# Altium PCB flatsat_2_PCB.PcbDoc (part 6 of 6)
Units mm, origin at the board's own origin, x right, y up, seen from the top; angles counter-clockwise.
Board outline 400 x 250 mm, 4 copper layers (Top Layer, FlatSat GND, FlatSat VCC, Bottom Layer), stack 2.102 mm thick; 196 components, 289 nets, 1724 pads, 1139 vias.
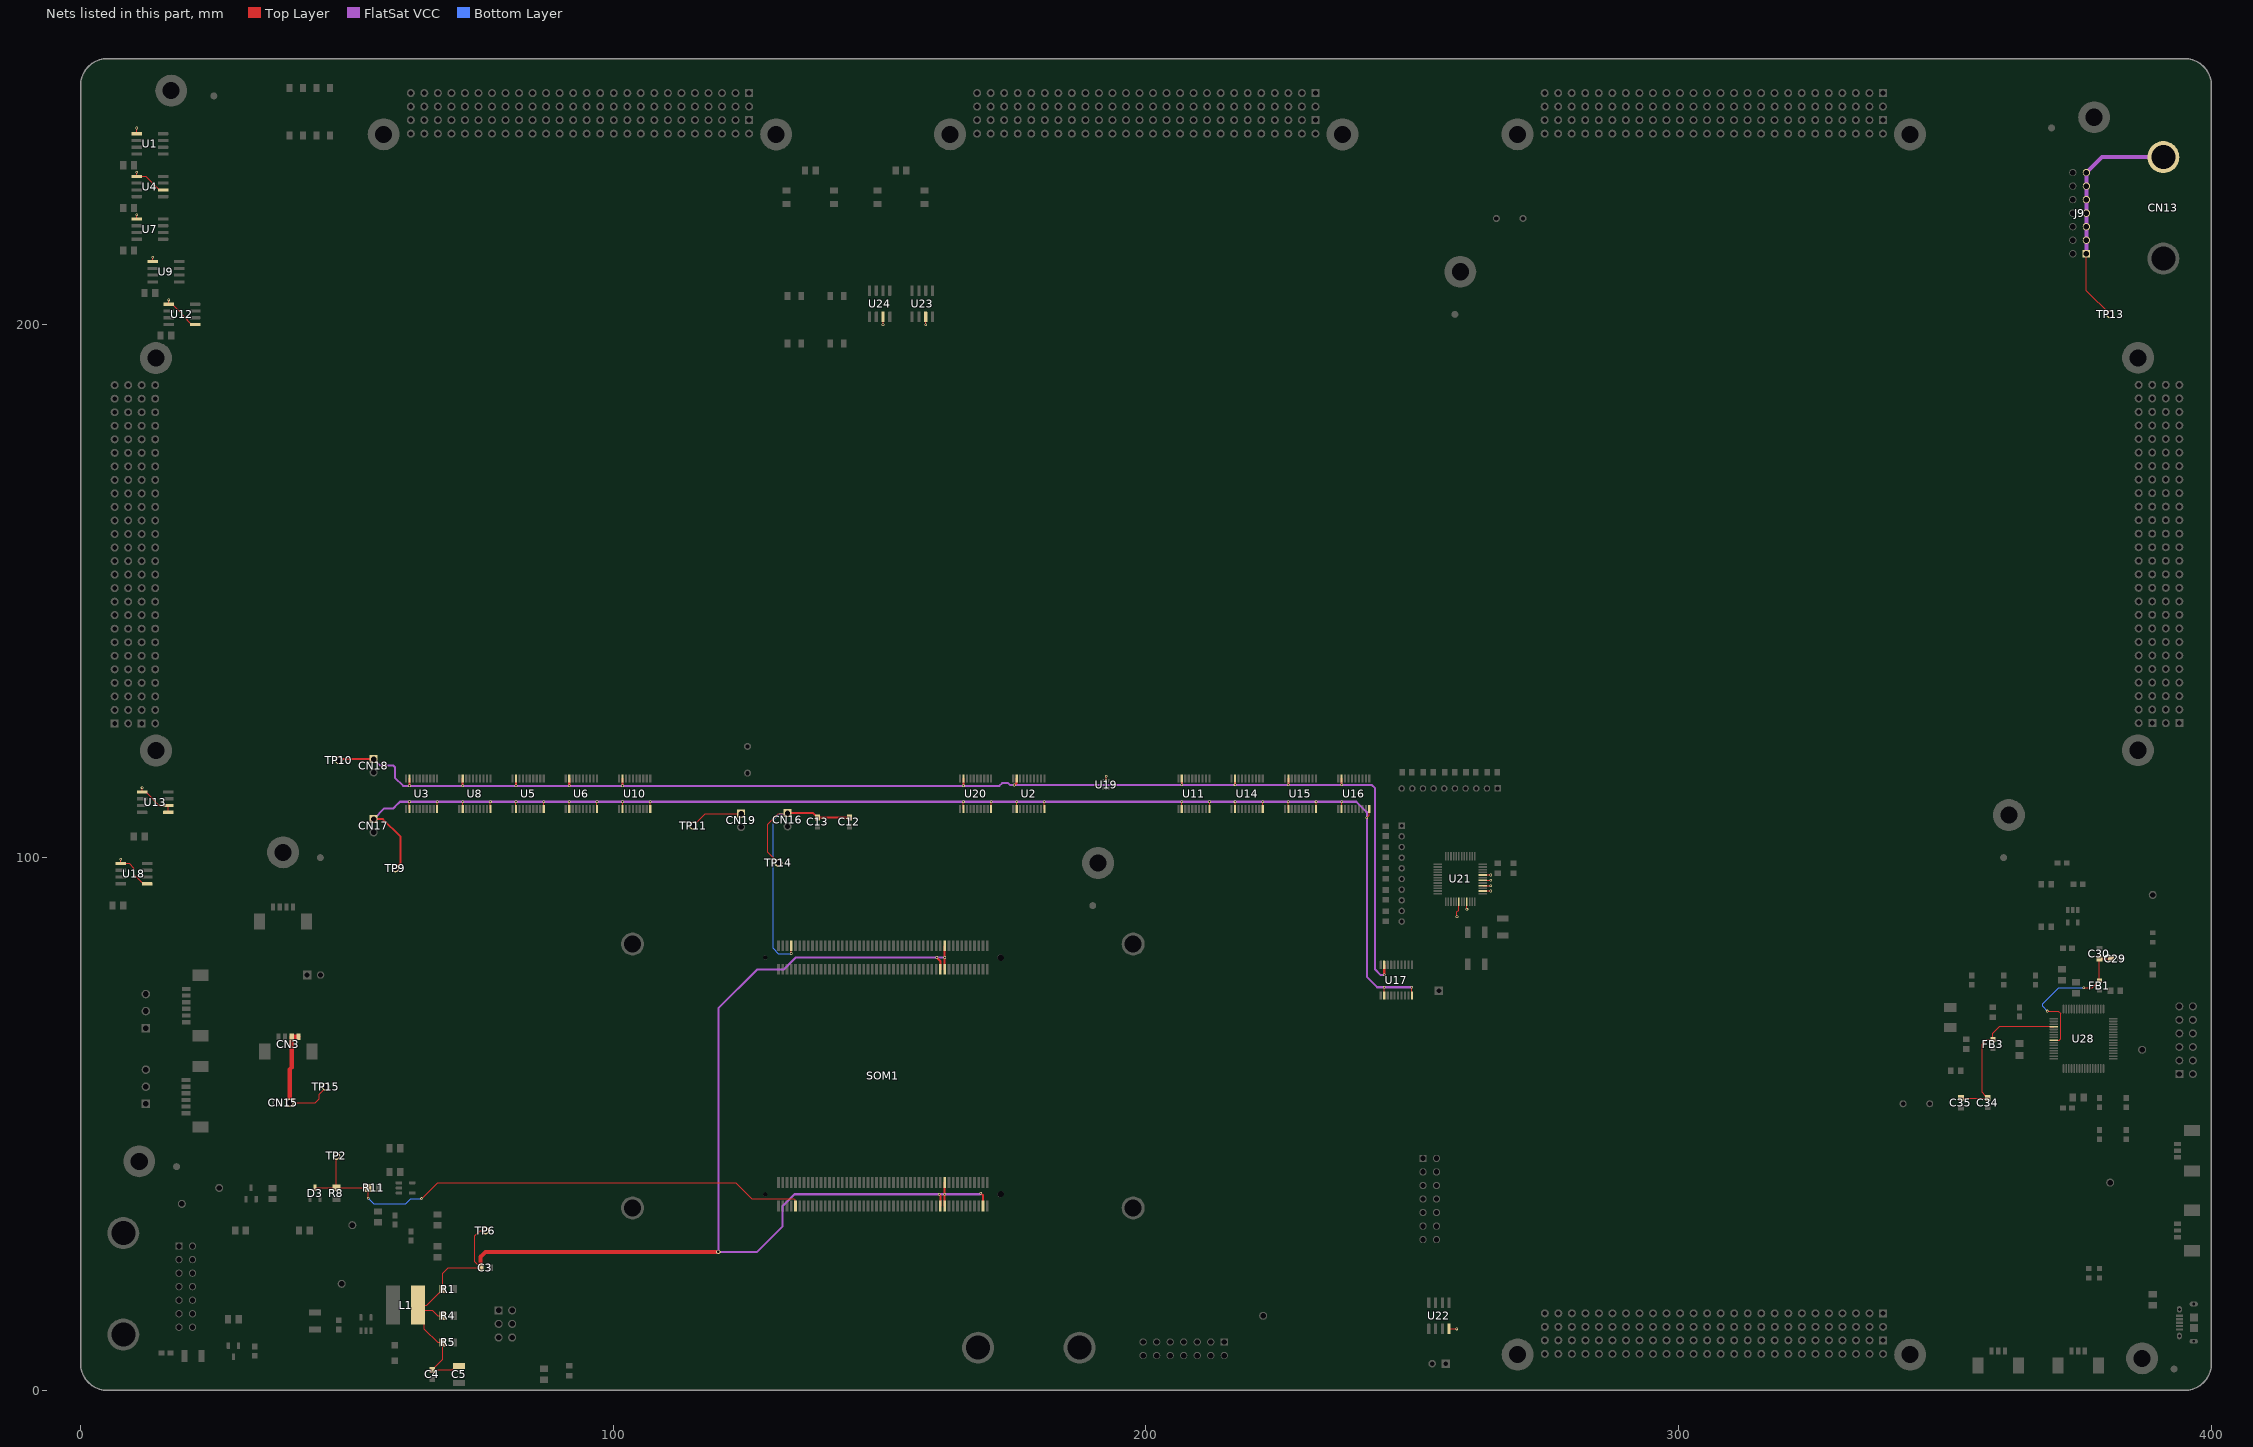
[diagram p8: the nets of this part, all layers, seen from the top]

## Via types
v1: diameter 0.508, hole 0.3, Top Layer to Bottom Layer, tented both sides, 1073 vias
v2: diameter 0.762, hole 0.45, Top Layer to Bottom Layer, tented both sides, 66 vias

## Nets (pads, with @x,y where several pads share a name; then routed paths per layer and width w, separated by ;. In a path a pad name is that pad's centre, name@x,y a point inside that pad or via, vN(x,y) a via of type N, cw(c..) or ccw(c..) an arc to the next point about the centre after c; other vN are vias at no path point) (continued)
V2_E: CN13.1 J9.1 J9.3 J9.5 J9.7 J9.9 J9.11 J9.13 TP13.1 | length 44.1
  Top Layer w0.203: J9.1@376.54,213.38 376.54,206.46 TP13.1@381,202
  FlatSat VCC w0.762: J9.1@376.54,213.38 J9.3@376.54,215.92 J9.5@376.54,218.46 J9.7@376.54,221 J9.9@376.54,223.54 J9.11@376.54,226.08 J9.13@376.54,228.62 379.445,231.525 CN13.1@391,231.525
VBAT: C12.1 C13.1 CN16.1 SOM1.JX1-7 TP14.1 | length 57.2
  Top Layer w0.203: TP14.1@131,99 129,101 129,106.285 130.985,108.27 132.616,108.27 CN16.1@132.703,108.357 ; v1(133.4,82.003) SOM1.JX1-7@133.4,83.45
  Top Layer w0.381: CN16.1@132.703,108.357 137.523,108.357 138.255,107.625 C13.1@138.33,107.625 ; C13.1@138.33,107.55 C12.1@144.33,107.55
  Bottom Layer w0.203: CN16.1@132.83,108.27 131.27,108.27 130,107 130,83 130.997,82.003 v1(133.4,82.003)
VCCA: CN17.1 TP9.1 U2.2 U2.10 U3.2 U3.10 U5.2 U5.10 U6.2 U6.10 U8.2 U8.10 U10.2 U10.10 U11.2 U11.10 U14.2 U14.10 U15.2 U15.10 U16.2 U16.10 U17.2 U17.10 U20.2 U20.10 | length 275.2
  Top Layer w0.203: U3.2@61.725,109.13 v1(61.725,110.496) ; U3.10@66.925,109.13 v1(66.925,110.496) ; U8.2@71.725,109.13 v1(71.725,110.496) ; U8.10@76.925,109.13 v1(76.925,110.496) ; U5.2@81.725,109.13 v1(81.725,110.496) ; U5.10@86.925,109.13 v1(86.925,110.496) ; U6.2@91.725,109.13 v1(91.725,110.496) ; U6.10@96.925,109.13 v1(96.925,110.496) ; U10.2@101.725,109.13 v1(101.725,110.496) ; U10.10@106.925,109.13 v1(106.925,110.496) ; U20.2@165.725,109.13 v1(165.725,110.496) ; U20.10@170.925,109.13 v1(170.925,110.496) ; U2.2@175.725,109.13 v1(175.725,110.496) ; U2.10@180.925,109.13 v1(180.925,110.496) ; U11.2@206.725,109.13 v1(206.725,110.496) ; U11.10@211.925,109.13 v1(211.925,110.496) ; U14.2@216.725,109.13 v1(216.725,110.496) ; U14.10@221.925,109.13 v1(221.925,110.496) ; U15.2@226.725,109.13 v1(226.725,110.496) ; U15.10@231.925,109.13 v1(231.925,110.496) ; U16.2@236.725,109.13 v1(236.725,110.496) ; v1(241.451,107.48) 241.925,107.953 U16.10@241.925,109.13 ; U17.2@244.725,74.13 v1(244.725,75.671) v1@244.725,75.725 ; U17.10@249.925,74.13 v1@249.925,75.725
  Top Layer w0.381: CN17.1@55,107.25 56.75,107.25 60,104 60,98.936 TP9.1@59.064,98
  FlatSat VCC w0.381: CN17.1@55,107.25 57.02,109.27 58.73,109.27 59,109.54 59.956,110.496 v1(61.725,110.496) v1(66.925,110.496) v1(71.725,110.496) v1(76.925,110.496) v1(81.725,110.496) v1(86.925,110.496) v1(91.725,110.496) v1(96.925,110.496) v1(101.725,110.496) v1(106.925,110.496) v1(165.725,110.496) v1(170.925,110.496) v1(175.725,110.496) v1(180.925,110.496) v1(206.725,110.496) v1(211.925,110.496) v1(216.725,110.496) v1(221.925,110.496) v1(226.725,110.496) v1(231.925,110.496) v1(236.725,110.496) 239.49,110.496 241.451,108.535 v1(241.451,107.48) 241.451,77.61 243.391,75.671 v1(244.725,75.671) v1(249.882,75.671)
VCCB: CN18.1 TP10.1 U2.19 U3.19 U5.19 U6.19 U8.19 U10.19 U11.19 U14.19 U15.19 U16.19 U17.19 U20.19 | length 251.2
  Top Layer w0.381: TP10.1@48.459,118.297 48.661,118.5 CN18.1@55,118.5 ; v1(61.725,113.475) U3.19@61.725,114.87 ; v1(71.725,113.475) U8.19@71.725,114.87 ; v1(81.725,113.475) U5.19@81.725,114.87 ; v1(91.725,113.475) U6.19@91.725,114.87 ; v1(101.725,113.475) U10.19@101.725,114.87 ; v1(165.725,113.475) U20.19@165.725,114.87 ; v1(175.272,113.635) 175.296,113.659 175.345,113.659 175.71,114.024 175.71,114.855 U2.19@175.725,114.87 ; v1(206.725,113.665) U11.19@206.725,114.87 ; v1(216.725,113.665) U14.19@216.725,114.87 ; v1(226.725,113.665) U15.19@226.725,114.87 ; v1(236.725,113.665) U16.19@236.725,114.87 ; v1(244.725,78) U17.19@244.725,79.87
  FlatSat VCC w0.381: CN18.1@55,118.5 56.23,117.27 58.73,117.27 59,117 59,115 60.525,113.475 v1(61.725,113.475) v1(71.725,113.475) v1(81.725,113.475) v1(91.725,113.475) v1(101.725,113.475) v1(165.725,113.475) 172.475,113.475 173,114 174.115,114 174.45,113.665 v1(206.725,113.665) v1(216.725,113.665) v1(226.725,113.665) v1(236.725,113.665) 242.335,113.665 243,113 243,79 244,78 v1(244.725,78)
VCCIO: C3.1 C4.1 C5.1 L1.2 R1.2 R4.2 R5.2 SOM1.JX1-78 SOM1.JX1-79 SOM1.JX1-80 SOM1.JX2-78 SOM1.JX2-79 SOM1.JX2-80 SOM1.JX2-98 TP6.1 | length 261.6
  Top Layer w0.203: C4.1@66,3.85 69.745,3.85 70.495,4.6 C5.1@71.045,4.6 ; C4.1@66,3.925 66.075,3.925 67.984,5.834 R5.2@67.984,9 67,9 64.543,11.457 64.543,14.806 L1.2@64.35,15 ; R4.2@67.984,14 67,14 66,15 L1.2@64.35,15 ; C3.1@75.075,23 69,23 67.984,21.984 R1.2@67.984,19 67.984,18.838 67.486,18.34 67.324,18.34 64.984,16 L1.2@63.349,16 L1.2@64.35,15 ; C3.1@75.075,23.075 74,24.15 74,29 75,30 TP6.1@76,30
  Top Layer w0.381: v1(160.737,81.263) 161.4,80.6 SOM1.JX1-78@161.4,79.05 ; v1(161.188,36.812) 161.4,36.6 SOM1.JX2-78@161.4,34.6 ; SOM1.JX2-80@162.2,34.6 v1(162.2,36.812) SOM1.JX2-79@162.2,39 ; SOM1.JX1-80@162.2,79.05 v1(162.2,81.263) SOM1.JX1-79@162.2,83.45 ; v1(169,37) 169.4,36.6 SOM1.JX2-98@169.4,34.6
  Top Layer w0.762: C3.1@75.075,23 75.075,23.075 75.075,25.075 76,26 v2(119.699,26)
  FlatSat VCC w0.381: v1(162.2,81.263) v1(160.737,81.263) 134.263,81.263 132,79 127,79 119.699,71.699 v2(119.699,26) 127,26 131.8,30.8 131.8,34.6 134.012,36.812 v1(161.188,36.812) v1(162.2,36.812) 168.812,36.812 v1(169,37)
VCCIO_EN: D3.3 R8.2 R11.2 SOM1.JX2-10 TP2.1 | length 102.7
  Top Layer w0.203: D3.3@44,38.055 R8.2@47.961,38.055 ; TP2.1@48,44 48,38.094 R8.2@47.961,38.055 ; v1(53.984,36.075) R11.2@53.984,38 53.968,38.016 R8.2@48,38.016 R8.2@47.961,38.055 ; v1(64,36) 67,39 123,39 126,36 134,36 134.119,35.881 134.119,34.681 SOM1.JX2-10@134.2,34.6
  Bottom Layer w0.203: v1(53.984,36.075) 55.059,35 61,35 62,36 v1(64,36)
VCHARG: CN3.3 CN3.4 CN15.1 TP15.1 | length 22.4
  Top Layer w0.203: CN15.1@39.25,54 44,54 44.781,54.781 44.781,55.581 TP15.1@46,56.8
  Top Layer w0.762: CN15.1@39.25,54 39.25,60.25 39.625,60.625 CN3.3@39.625,66.375 CN3.4@40.875,66.375 ; TP15.1@46,56.8 TP15.1@46,57
VPHY: C34.1 C35.1 FB3.2 U28.4 | length 31
  Top Layer w0.203: C35.1@353,54.925 353.075,54.85 C34.1@358,54.85 ; C34.1@357.925,54.925 357.502,55.348 357.502,55.423 357,55.925 357,65 357.889,65.889 FB3.2@359,65.889 359,67 360.306,68.306 369.668,68.306 369.724,68.25 U28.4@370.425,68.25
VPLL: C29.1 C30.1 FB1.2 U28.9 | length 29.4
  Top Layer w0.203: v1(369.2,71.2) 371.3,71.2 371.7,70.8 371.7,66 371.45,65.75 U28.9@370.425,65.75 ; v1(376.043,75.565) 377.626,75.565 378.95,76.889 FB1.2@379,76.889 C30.1@379,81.075 379.075,81 C29.1@381.15,81
  Bottom Layer w0.203: v1(369.2,71.2) 368.322,72.078 368.322,72.547 371.339,75.565 v1(376.043,75.565)
VS: CN19.1 TP11.1 U1.5 U4.2 U4.5 U7.5 U9.5 U12.1 U12.5 U13.1 U13.2 U13.5 U18.1 U18.5 U19.5 U21.2 U21.4 U21.6 U21.8 U21.42 U21.45 U22.8 U23.3 U24.3 | length 58.3
  Top Layer w0.203: v1(7.53,99.702) U18.5@7.53,98.905 9.095,98.905 10,98 10,96.88 11.785,95.095 U18.1@12.47,95.095 ; U7.5@10.53,219.905 v1(10.53,220.702) ; v1(10.53,228.702) U4.5@10.53,227.905 12.245,227.905 14.785,225.365 U4.2@15.47,225.365 ; U1.5@10.53,235.905 v1(10.53,236.98) ; v1(11.53,113.126) U13.5@11.53,112.328 12.215,112.328 14.755,109.788 U13.2@16.47,109.788 U13.1@16.47,108.518 ; U9.5@13.53,211.905 v1(13.53,212.702) ; v1(16.53,204.702) U12.5@16.53,203.905 17.215,203.905 19,202.12 19,202 20,201 20,200.88 20.785,200.095 U12.1@21.47,200.095 ; TP11.1@115,106 117.25,108.25 CN19.1@124,108.25 ; v1(150.635,200.07) U24.3@150.635,201.53 ; v1(158.635,200.07) U23.3@158.635,201.53 ; U19.5@192.5,114.47 192.517,114.487 192.517,115.251 v1(192.534,115.267) ; U22.8@256.905,11.525 v1(258.365,11.525) ; v1(258.379,88.935) 258.379,89.84 258.68,90.141 258.68,91.68 U21.42@258.75,91.75 ; v1(260.25,90.29) U21.45@260.25,91.75 ; U21.2@263.25,93.75 v1(264.71,93.75) ; U21.4@263.25,94.75 v1(264.71,94.75) ; U21.6@263.25,95.75 v1(264.71,95.75) ; U21.8@263.25,96.75 v1(264.71,96.75)
pads on no net: CN3.0 CN4.0 CN5.0 CN6.0 CN7.0 CN8.0 CN9.4 CN10.0 CN11.0 D2.2 D3.2 FD1.FD0 FD2.FD0 FD3.FD0 FD4.FD0 FD5.FD0 FD6.FD0 FD7.FD0 FD8.FD0 J4.14 MEC1.0 MEC2.0 MEC3.0 MEC4.0 MEC5.0 MEC6.0 MEC7.0 MEC8.0 SOM1.0 SOM1.JX1-1 SOM1.JX1-2 SOM1.JX1-3 SOM1.JX1-4 SOM1.JX1-6 SOM1.JX1-8 SOM1.JX1-9 SOM1.JX1-10 SOM1.JX1-87 SOM1.JX1-88 SOM1.JX1-89 SOM1.JX1-90 SOM1.JX1-91 SOM1.JX1-92 SOM1.JX1-93 SOM1.JX1-94 SOM1.JX2-9 SOM1.JX2-11 SOM1.JX2-13 SOM1.JX2-14 SOM1.JX2-93 SOM1.JX2-94 SOM1.JX2-95 SOM1.JX2-96 SOM1.JX2-97 SOM1.JX2-99 SOM1.JX2-100 U2.8 U2.9 U2.12 U2.13 U16.8 U16.9 U16.12 U16.13 U17.6 U17.7 U17.8 U17.9 U17.12 U17.13 U17.14 U17.15 U19.3 U20.6 U20.7 U20.8 U20.9 U20.12 U20.13 U20.14 U20.15 U21.10 U23.5 U23.8 U24.5 U24.8 U28.18 U28.19 U28.21 U28.22 U28.23 U28.24 U28.28 U28.29 U28.30 U28.32 U28.33 U28.34 U28.36 U28.40 U28.41 U28.43 U28.44 U28.45 U28.46 U28.53 U28.54 U28.55 U28.57 U28.58 U28.59 U28.60 U28.62

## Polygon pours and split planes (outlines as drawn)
VS on FlatSat VCC "VS_L03_P011" (solid, pour order 11): 0,245 cw(c5,245) 5,250 395,250 cw(c395,245) 400,245 400,5 cw(c395,5) 395,0 5,0 cw(c5,5) 0,5
USB_3.3V on FlatSat VCC "USB_3.3V_L03_P010" (solid, pour order 10): 395,0 ccw(c395,5) 400,5 400,113 341,113 341,0
5V on FlatSat VCC "5V_L03_P009" (solid, pour order 9): 5,0 cw(c5,5) 0,5 0,45 52,45 52,51 125,51 125,88 203,88 203,24 104,24 104,0
no net on FlatSat VCC "NONET_L03_P001" (solid, pour order 1): 3,159
no net on FlatSat VCC "NONET_L03_P000" (solid, pour order 0): 3,159
GND on FlatSat GND "GND_L02_P008" (solid, pour order 8): 395,0 ccw(c395,5) 400,5 400,245 ccw(c395,245) 395,250 5,250 ccw(c5,245) 0,245 0,5 ccw(c5,5) 5,0
PC104_GND on FlatSat GND "PC104_GND_L02_P007" (solid, pour order 7): 2.63,120.108 269.748,120.108 269.748,2.223 343.432,2.223 343.432,120.108 398,120.108 398,193.792 343.432,193.792 343.432,247.29 269.748,247.29 269.748,193.792 236.892,193.792 236.892,247.29 163.208,247.29 163.208,193.792 130.572,193.792 130.572,247.29 56.888,247.29 56.888,193.792 2.635,193.792 2.63,193.787
no net on FlatSat GND "NONET_L02_P005" (solid, pour order 5): 3,165
no net on FlatSat GND "NONET_L02_P004" (solid, pour order 4): 3,159
no net on FlatSat GND "NONET_L02_P003" (solid, pour order 3): 3,159
no net on FlatSat GND "NONET_L02_P002" (solid, pour order 2): 3,159
GND on Top Layer "GND_L01_P012" (solid, pour order 12): 395,250 cw(c395,245) 400,245 400,5 cw(c395,5) 395,0 5,0 cw(c5,5) 0,5 0,245 cw(c5,245) 5,250
GND on Bottom Layer "GND_L04_P013" (solid, pour order 13): 0,245 cw(c5,245) 5,250 395,250 cw(c395,245) 400,245 400,5 cw(c395,5) 395,0 5,0 cw(c5,5) 0,5

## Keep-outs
Keep-Out Layer:
  lines w0.254: 5,250 ccw(c5,245) 0,245 0,5 ccw(c5,5) 5,0 395,0 ccw(c395,5) 400,5 400,245 ccw(c395,245) 395,250 5,250 ; 5,250 5,250

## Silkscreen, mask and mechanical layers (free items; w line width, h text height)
Top Overlay:
  drawing of 1047 lines, arcs and shapes, not listed
  text "Switches for short circuit CANH and CANL with  / GND together" at 29,247 h0.5
  text "+" at 391.254,239 h1.52
  text "Switches for enable or disable terminal resistor" at 128.432,230.428 h0.5
  text "-" at 372.498,227.994 h1.52 r90
  text "+" at 379.74,227.994 h1.52 r90
  text "-" at 372.498,225.744 h1.52 r90
  text "+" at 379.74,225.744 h1.52 r90
  text "Slot 2" at 60.511,223.874 h3
  text "Slot 3" at 166.831,223.874 h3
  text "Slot 4" at 273.371,223.874 h3
  text "-" at 372.498,223.244 h1.52 r90
  text "+" at 379.74,223.244 h1.52 r90
  text "-" at 372.498,220.494 h1.52 r90
  text "+" at 379.74,220.494 h1.52 r90
  text "Switches for short circuit CANH and CANL together" at 129.1,218.267 h0.5
  text "-" at 372.498,217.994 h1.52 r90
  text "+" at 379.74,217.994 h1.52 r90
  text "-" at 372.498,215.494 h1.52 r90
  text "+" at 379.74,215.494 h1.52 r90
  text "Switches for break the CAN BUS lines" at 121.432,213.959 h0.5
  text "-" at 372.498,212.954 h1.52 r90
  text "+" at 379.74,212.954 h1.52 r90
  text "EXTERNAL  / POWER SUPPLY" at 373,211 h1.52 r270
  text "FlatSat Platform 2 / v0.1" at 289,210 h1.2
  text "SpaceLab UFSC  2021" at 287.983,207.351 h1.2
  text "-" at 391.254,204.492 h1.52
  text "Current, voltage and power sensors" at 4,201 h0.5
  text "Slot 5" at 374.319,190.224 h3 r270
  text "WARNING: Inverted PC104 pinout" at 32,127.649 h4.3 r90
  text "Slot 1" at 28.046,124.035 h3 r90
  text "Table of non-configurable PC104 pins" at 283.485,121.592 h3
  text "+" at 54.367,121.5 h1.52
  text "H" at 278.459,116.992 h2.25
  text "1" at 279.923,116.992 h2.25
  text "F" at 288.113,116.992 h2.25
  text "U" at 289.369,116.992 h2.25
  text "N" at 290.833,116.992 h2.25
  text "C" at 292.297,116.992 h2.25
  text "T" at 293.771,116.992 h2.25
  text "I" at 295.027,116.992 h2.25
  text "O" at 295.65,116.992 h2.25
  text "N" at 297.114,116.992 h2.25
  text "H" at 305.792,116.992 h2.25
  text "2" at 307.256,116.992 h2.25
  text "F" at 315.446,116.992 h2.25
  text "U" at 316.703,116.992 h2.25
  text "N" at 318.166,116.992 h2.25
  text "C" at 319.63,116.992 h2.25
  text "T" at 321.104,116.992 h2.25
  text "I" at 322.36,116.992 h2.25
  text "O" at 322.984,116.992 h2.25
  text "N" at 324.447,116.992 h2.25
  text "VCCB" at 51.746,114.254 h1.52 r90
  text "Current, voltage and power sensors" at 1.305,113.743 h0.5
  text "1" at 279.198,112.55 h2.25
  text "C" at 286.734,112.55 h2.25
  text "A" at 288.198,112.55 h2.25
  text "N" at 289.662,112.55 h2.25
  text "L" at 291.135,112.55 h2.25
  text "_" at 292.392,112.55 h2.25
  text "C" at 293.43,112.55 h2.25
  text "H" at 294.904,112.55 h2.25
  text "N" at 296.368,112.55 h2.25
  text "_" at 297.832,112.55 h2.25
  text "1" at 298.88,112.55 h2.25
  text "2" at 306.532,112.55 h2.25
  text "C" at 314.067,112.55 h2.25
  text "A" at 315.531,112.55 h2.25
  text "N" at 316.995,112.55 h2.25
  text "L" at 318.469,112.55 h2.25
  text "_" at 319.725,112.55 h2.25
  text "C" at 320.764,112.55 h2.25
  text "H" at 322.237,112.55 h2.25
  text "N" at 323.701,112.55 h2.25
  text "_" at 325.165,112.55 h2.25
  text "2" at 326.214,112.55 h2.25
  text "-" at 55.641,111.984 h1.52 r90
  text "GND" at 247.582,111.376 h0.85 r270
  text "CH9" at 249.582,111.376 h0.85 r270
  text "GND" at 251.582,111.376 h0.85 r270
  text "CH7" at 253.582,111.376 h0.85 r270
  text "GND" at 255.582,111.376 h0.85 r270
  text "CH5" at 257.582,111.376 h0.85 r270
  text "GND" at 259.582,111.376 h0.85 r270
  text "CH3" at 261.582,111.376 h0.85 r270
  text "GND" at 263.582,111.376 h0.85 r270
  text "CH1" at 265.582,111.376 h0.85 r270
  text "+" at 132.07,111.357 h1.52
  text "+" at 123.367,111.25 h1.52
  text "+" at 54.367,110.25 h1.52
  text "Ambient temperature  / sensor" at 189.378,108.47 h0.5
  text "3" at 279.198,108.109 h2.25
  text "C" at 286.624,108.109 h2.25
  text "A" at 288.088,108.109 h2.25
  text "N" at 289.552,108.109 h2.25
  text "H" at 291.025,108.109 h2.25
  text "_" at 292.489,108.109 h2.25
  text "C" at 293.538,108.109 h2.25
  text "H" at 295.002,108.109 h2.25
  text "N" at 296.466,108.109 h2.25
  text "_" at 297.93,108.109 h2.25
  text "1" at 298.978,108.109 h2.25
  text "6" at 306.532,108.109 h2.25
  text "C" at 313.957,108.109 h2.25
  text "A" at 315.421,108.109 h2.25
  text "N" at 316.885,108.109 h2.25
  text "H" at 318.359,108.109 h2.25
  text "_" at 319.823,108.109 h2.25
  text "C" at 320.871,108.109 h2.25
  text "H" at 322.335,108.109 h2.25
  text "N" at 323.799,108.109 h2.25
  text "_" at 325.263,108.109 h2.25
  text "2" at 326.312,108.109 h2.25
  text "CH11" at 249.624,105.582 h0.85
  text "3.3V" at 120.746,104.254 h1.52 r90
  text "VBAT" at 129.746,104.254 h1.52 r90
  text "2" at 278.669,103.668 h2.25
  text "9" at 279.717,103.668 h2.25
  text "G" at 291.171,103.668 h2.25
  text "N" at 292.635,103.668 h2.25
  text "D" at 294.099,103.668 h2.25
  text "2" at 306.002,103.668 h2.25
  text "5" at 307.051,103.668 h2.25
  text "P" at 312.378,103.668 h2.25
  text "A" at 313.634,103.668 h2.25
  text "Y" at 315.098,103.668 h2.25
  text "L" at 316.562,103.668 h2.25
  text "O" at 317.818,103.668 h2.25
  text "A" at 319.292,103.668 h2.25
  text "D" at 320.756,103.668 h2.25
  text "S" at 322.22,103.668 h2.25
  text "_" at 323.476,103.668 h2.25
  text "V" at 324.525,103.668 h2.25
  text "C" at 325.989,103.668 h2.25
  text "C" at 327.453,103.668 h2.25
  text "GND" at 249.624,103.582 h0.85
  text "VCCA" at 51.746,103.254 h1.52 r90
  text "-" at 133.344,101.841 h1.52 r90
  text "-" at 124.641,101.734 h1.52 r90
  text "CH13" at 249.624,101.582 h0.85
  text "-" at 55.641,100.734 h1.52 r90
  text "GND" at 249.624,99.582 h0.85
  text "3" at 278.669,99.227 h2.25
  text "0" at 279.717,99.227 h2.25
  text "G" at 291.171,99.227 h2.25
  text "N" at 292.635,99.227 h2.25
  text "D" at 294.099,99.227 h2.25
  text "2" at 306.002,99.227 h2.25
  text "6" at 307.051,99.227 h2.25
  text "P" at 312.378,99.227 h2.25
  text "A" at 313.634,99.227 h2.25
  text "Y" at 315.098,99.227 h2.25
  text "L" at 316.562,99.227 h2.25
  text "O" at 317.818,99.227 h2.25
  text "A" at 319.292,99.227 h2.25
  text "D" at 320.756,99.227 h2.25
  text "S" at 322.22,99.227 h2.25
  text "_" at 323.476,99.227 h2.25
  text "V" at 324.525,99.227 h2.25
  text "C" at 325.989,99.227 h2.25
  text "C" at 327.453,99.227 h2.25
  text "CH15" at 249.624,97.582 h0.85
  text "GND" at 249.624,95.582 h0.85
  text "3" at 278.669,94.786 h2.25
  text "1" at 279.717,94.786 h2.25
  text "G" at 291.171,94.786 h2.25
  text "N" at 292.635,94.786 h2.25
  text "D" at 294.099,94.786 h2.25
  text "2" at 306.002,94.786 h2.25
  text "7" at 307.051,94.786 h2.25
  text "E" at 313.857,94.786 h2.25
  text "P" at 315.114,94.786 h2.25
  text "S" at 316.37,94.786 h2.25
  text "_" at 317.626,94.786 h2.25
  text "B" at 318.674,94.786 h2.25
  text "E" at 320.138,94.786 h2.25
  text "_" at 321.395,94.786 h2.25
  text "V" at 322.443,94.786 h2.25
  text "C" at 323.907,94.786 h2.25
  text "C" at 325.371,94.786 h2.25
  text "CH17" at 249.624,93.582 h0.85
  text "GND" at 249.624,91.582 h0.85
  text "3" at 278.669,90.344 h2.25
  text "2" at 279.717,90.344 h2.25
  text "G" at 291.171,90.344 h2.25
  text "N" at 292.635,90.344 h2.25
  text "D" at 294.099,90.344 h2.25
  text "2" at 306.002,90.344 h2.25
  text "8" at 307.051,90.344 h2.25
  text "E" at 313.857,90.344 h2.25
  text "P" at 315.114,90.344 h2.25
  text "S" at 316.37,90.344 h2.25
  text "_" at 317.626,90.344 h2.25
  text "B" at 318.674,90.344 h2.25
  text "E" at 320.138,90.344 h2.25
  text "_" at 321.395,90.344 h2.25
  text "V" at 322.443,90.344 h2.25
  text "C" at 323.907,90.344 h2.25
  text "C" at 325.371,90.344 h2.25
  text "CH19" at 249.624,89.582 h0.85
  text "GND" at 249.624,87.582 h0.85
  text "4" at 278.669,85.903 h2.25
  text "1" at 279.717,85.903 h2.25
  text "S" at 287.473,85.903 h2.25
  text "D" at 288.73,85.903 h2.25
  text "A" at 290.193,85.903 h2.25
  text "_" at 291.657,85.903 h2.25
  text "C" at 292.706,85.903 h2.25
  text "H" at 294.17,85.903 h2.25
  text "N" at 295.644,85.903 h2.25
  text "_" at 297.107,85.903 h2.25
  text "1" at 298.156,85.903 h2.25
  text "2" at 306.002,85.903 h2.25
  text "9" at 307.051,85.903 h2.25
  text "G" at 318.505,85.903 h2.25
  text "N" at 319.968,85.903 h2.25
  text "D" at 321.432,85.903 h2.25
  text "4" at 278.669,81.462 h2.25
  text "3" at 279.717,81.462 h2.25
  text "S" at 287.583,81.462 h2.25
  text "C" at 288.839,81.462 h2.25
  text "L" at 290.303,81.462 h2.25
  text "_" at 291.56,81.462 h2.25
  text "C" at 292.608,81.462 h2.25
  text "H" at 294.072,81.462 h2.25
  text "N" at 295.536,81.462 h2.25
  text "_" at 297.01,81.462 h2.25
  text "1" at 298.048,81.462 h2.25
  text "3" at 306.002,81.462 h2.25
  text "0" at 307.051,81.462 h2.25
  text "G" at 318.505,81.462 h2.25
  text "N" at 319.968,81.462 h2.25
  text "D" at 321.432,81.462 h2.25
  text "4" at 278.669,77.021 h2.25
  text "5" at 279.717,77.021 h2.25
  text "O" at 287.683,77.021 h2.25
  text "B" at 289.147,77.021 h2.25
  text "D" at 290.611,77.021 h2.25
  text "H" at 292.085,77.021 h2.25
  text "_" at 293.549,77.021 h2.25
  text "V" at 294.597,77.021 h2.25
  text "C" at 296.061,77.021 h2.25
  text "C" at 297.525,77.021 h2.25
  text "3" at 306.002,77.021 h2.25
  text "1" at 307.051,77.021 h2.25
  text "G" at 318.505,77.021 h2.25
  text "N" at 319.968,77.021 h2.25
  text "D" at 321.432,77.021 h2.25
  text "INTERRUPT" at 256.756,75.104 h0.85
  text "RBF" at 41.728,74.545 h1.52
  text "NO" at 14.254,73.254 h1.52
  text "4" at 278.669,72.58 h2.25
  text "6" at 279.717,72.58 h2.25
  text "O" at 287.683,72.58 h2.25
  text "B" at 289.147,72.58 h2.25
  text "D" at 290.611,72.58 h2.25
  text "H" at 292.085,72.58 h2.25
  text "_" at 293.549,72.58 h2.25
  text "V" at 294.597,72.58 h2.25
  text "C" at 296.061,72.58 h2.25
  text "C" at 297.525,72.58 h2.25
  text "3" at 306.002,72.58 h2.25
  text "2" at 307.051,72.58 h2.25
  text "G" at 318.505,72.58 h2.25
  text "N" at 319.968,72.58 h2.25
  text "D" at 321.432,72.58 h2.25
  text "RX3" at 390.847,71.862 h0.5
  text "TX4" at 398.219,71.729 h0.5
  text "CM" at 14.254,70.254 h1.52
  text "TX3" at 390.847,69.322 h0.5
  text "RX4" at 398.219,69.189 h0.5
  text "4" at 278.669,68.138 h2.25
  text "7" at 279.717,68.138 h2.25
  text "E" at 288.533,68.138 h2.25
  text "D" at 289.789,68.138 h2.25
  text "C" at 291.253,68.138 h2.25
  text "_" at 292.717,68.138 h2.25
  text "V" at 293.765,68.138 h2.25
  text "C" at 295.229,68.138 h2.25
  text "C" at 296.703,68.138 h2.25
  text "3" at 306.002,68.138 h2.25
  text "5" at 307.051,68.138 h2.25
  text "A" at 315.866,68.138 h2.25
  text "N" at 317.33,68.138 h2.25
  text "T" at 318.794,68.138 h2.25
  text "_" at 320.05,68.138 h2.25
  text "V" at 321.099,68.138 h2.25
  text "C" at 322.563,68.138 h2.25
  text "C" at 324.036,68.138 h2.25
  text "NC" at 14.254,67.254 h1.52
  text "Thermocouples" at 262.99,67.229 h0.5
  text "RX2" at 390.847,66.782 h0.5
  text "GND" at 398.219,66.649 h0.5
  text "TX2" at 390.847,64.242 h0.5
  text "GND" at 398.219,64.109 h0.5
  text "4" at 278.669,63.697 h2.25
  text "8" at 279.717,63.697 h2.25
  text "E" at 288.533,63.697 h2.25
  text "D" at 289.789,63.697 h2.25
  text "C" at 291.253,63.697 h2.25
  text "_" at 292.717,63.697 h2.25
  text "V" at 293.765,63.697 h2.25
  text "C" at 295.229,63.697 h2.25
  text "C" at 296.703,63.697 h2.25
  text "3" at 306.002,63.697 h2.25
  text "6" at 307.051,63.697 h2.25
  text "A" at 315.866,63.697 h2.25
  text "N" at 317.33,63.697 h2.25
  text "T" at 318.794,63.697 h2.25
  text "_" at 320.05,63.697 h2.25
  text "V" at 321.099,63.697 h2.25
  text "C" at 322.563,63.697 h2.25
  text "C" at 324.036,63.697 h2.25
  text "RX1" at 390.847,61.702 h0.5
  text "GND" at 398.219,61.569 h0.5
  text "4" at 278.669,59.256 h2.25
  text "9" at 279.717,59.256 h2.25
  text "R" at 289.162,59.256 h2.25
  text "D" at 290.626,59.256 h2.25
  text "_" at 292.09,59.256 h2.25
  text "V" at 293.139,59.256 h2.25
  text "C" at 294.603,59.256 h2.25
  text "C" at 296.076,59.256 h2.25
  text "4" at 306.002,59.256 h2.25
  text "5" at 307.051,59.256 h2.25
  text "B" at 315.866,59.256 h2.25
  text "A" at 317.33,59.256 h2.25
  text "T" at 318.794,59.256 h2.25
  text "_" at 320.05,59.256 h2.25
  text "V" at 321.099,59.256 h2.25
  text "C" at 322.563,59.256 h2.25
  text "C" at 324.036,59.256 h2.25
  text "TX1" at 390.847,59.162 h0.5
  text "NO" at 14.26,59.054 h1.52
  text "GND" at 398.219,59.029 h0.5
  text "CM" at 14.26,56.054 h1.52
  text "5" at 278.669,54.815 h2.25
  text "0" at 279.717,54.815 h2.25
  text "R" at 289.162,54.815 h2.25
  text "D" at 290.626,54.815 h2.25
  text "_" at 292.09,54.815 h2.25
  text "V" at 293.139,54.815 h2.25
  text "C" at 294.603,54.815 h2.25
  text "C" at 296.076,54.815 h2.25
  text "4" at 306.002,54.815 h2.25
  text "6" at 307.051,54.815 h2.25
  text "B" at 315.866,54.815 h2.25
  text "A" at 317.33,54.815 h2.25
  text "T" at 318.794,54.815 h2.25
  text "_" at 320.05,54.815 h2.25
  text "V" at 321.099,54.815 h2.25
  text "C" at 322.563,54.815 h2.25
  text "C" at 324.036,54.815 h2.25
  text "+" at 42.25,54.633 h1.52 r270
  text "-" at 32.734,53.359 h1.52
  text "NC" at 14.26,53.054 h1.52
  text "5" at 278.669,50.374 h2.25
  text "1" at 279.717,50.374 h2.25
  text "B" at 287.054,50.374 h2.25
  text "E" at 288.517,50.374 h2.25
  text "_" at 289.774,50.374 h2.25
  text "R" at 290.822,50.374 h2.25
  text "F" at 292.286,50.374 h2.25
  text "_" at 293.542,50.374 h2.25
  text "V" at 294.591,50.374 h2.25
  text "C" at 296.055,50.374 h2.25
  text "C" at 297.519,50.374 h2.25
  text "4" at 306.002,50.374 h2.25
  text "9" at 307.051,50.374 h2.25
  text "S" at 314.807,50.374 h2.25
  text "D" at 316.063,50.374 h2.25
  text "A" at 317.527,50.374 h2.25
  text "_" at 318.991,50.374 h2.25
  text "C" at 320.039,50.374 h2.25
  text "H" at 321.503,50.374 h2.25
  text "N" at 322.977,50.374 h2.25
  text "_" at 324.441,50.374 h2.25
  text "2" at 325.489,50.374 h2.25
  text "CHARGE" at 34.254,48.254 h1.52
  text "5" at 278.669,45.932 h2.25
  text "2" at 279.717,45.932 h2.25
  text "B" at 287.054,45.932 h2.25
  text "E" at 288.517,45.932 h2.25
  text "_" at 289.774,45.932 h2.25
  text "R" at 290.822,45.932 h2.25
  text "F" at 292.286,45.932 h2.25
  text "_" at 293.542,45.932 h2.25
  text "V" at 294.591,45.932 h2.25
  text "C" at 296.055,45.932 h2.25
  text "C" at 297.519,45.932 h2.25
  text "5" at 306.002,45.932 h2.25
  text "1" at 307.051,45.932 h2.25
  text "S" at 314.917,45.932 h2.25
  text "C" at 316.173,45.932 h2.25
  text "L" at 317.637,45.932 h2.25
  text "_" at 318.893,45.932 h2.25
  text "C" at 319.941,45.932 h2.25
  text "H" at 321.405,45.932 h2.25
  text "N" at 322.869,45.932 h2.25
  text "_" at 324.343,45.932 h2.25
  text "2" at 325.382,45.932 h2.25
  text "EXTRA I/O PINS" at 256.254,45.746 h1.52 r270
  text "+" at 7.494,36.398 h1.52
  text "5V" at 20.746,29.254 h1.52 r90
  text "+" at 15.26,27.506 h1.52 r270
  text "-" at 22.502,27.506 h1.52 r270
  text "+" at 15.26,24.966 h1.52 r270
  text "-" at 22.502,24.966 h1.52 r270
  text "+" at 15.26,22.466 h1.52 r270
  text "-" at 22.502,22.466 h1.52 r270
  text "+" at 15.26,19.966 h1.52 r270
  text "-" at 22.502,19.966 h1.52 r270
  text "Slot 6" at 273.371,19.874 h3
  text "+" at 15.26,17.216 h1.52 r270
  text "-" at 22.502,17.216 h1.52 r270
  text "+" at 15.26,14.716 h1.52 r270
  text "-" at 22.502,14.716 h1.52 r270
  text "+" at 15.26,12.466 h1.52 r270
  text "-" at 22.502,12.466 h1.52 r270
  text "+" at 200.085,12.27 h1.52 r180
  text "+" at 202.335,12.27 h1.52 r180
  text "+" at 204.835,12.27 h1.52 r180
  text "+" at 207.585,12.27 h1.52 r180
  text "+" at 210.085,12.27 h1.52 r180
  text "+" at 212.585,12.27 h1.52 r180
  text "+" at 215.125,12.27 h1.52 r180
  text "-" at 195.541,8.641 h1.52 r180
  text "+" at 161.602,7.494 h1.52 r90
  text "EXTERNAL  / POWER SUPPLY" at 217,6 h1.52
  text "-" at 200.085,5.027 h1.52 r180
  text "-" at 202.335,5.027 h1.52 r180
  text "-" at 204.835,5.027 h1.52 r180
  text "-" at 207.585,5.027 h1.52 r180
  text "-" at 210.085,5.027 h1.52 r180
  text "-" at 212.585,5.027 h1.52 r180
  text "-" at 215.125,5.027 h1.52 r180
  text "-" at 8.641,2.459 h1.52 r90
  text "RS485" at 251.535,1.65 h1.52
Mechanical 6:
  the board outline again, w0.254
Drill Drawing:
  drawing of 191 lines, arcs and shapes, not listed
  text "Symbol" at 457.476,319.855 h1.83
  text "Count" at 470.326,319.855 h1.83
  text "Hole Size" at 486.831,319.855 h1.83
  text "Plated" at 516.033,319.855 h1.83
  text "Hole Type" at 528.882,319.855 h1.83
  text "Drill Layer Pair" at 547.521,319.855 h1.83
  text "Via/Pad" at 585.609,319.855 h1.83
  text "Pad Shape" at 600.591,319.855 h1.83
  text "Template" at 619.535,319.855 h1.83
  text "Description" at 648.482,319.855 h1.83
  text "Hole Tolerance (+)" at 670.168,319.855 h1.83
  text "Hole Tolerance (-)" at 704.041,319.855 h1.83
  text "Hole Length" at 737.915,319.855 h1.83
  text "Routed Path Length" at 765.847,319.855 h1.83
  text "2" at 470.326,316.045 h1.52
  text "19.69mil (0.500mm)" at 486.831,316.045 h1.52
  text "PTH" at 516.033,316.045 h1.52
  text "Slot" at 528.882,316.045 h1.52
  text "Top Layer - Bottom Layer" at 547.521,316.045 h1.52
  text "Pad" at 585.609,316.045 h1.52
  text "Rounded" at 600.591,316.045 h1.52
  text "r90_160h50_120r100" at 619.535,316.045 h1.52
  text "47.24mil (1.200mm)" at 737.915,316.045 h1.52
  text "27.56mil (0.700mm)" at 765.847,316.045 h1.52
  text "2" at 470.326,312.235 h1.52
  text "21.65mil (0.550mm)" at 486.831,312.235 h1.52
  text "PTH" at 516.033,312.235 h1.52
  text "Slot" at 528.882,312.235 h1.52
  text "Top Layer - Bottom Layer" at 547.521,312.235 h1.52
  text "Pad" at 585.609,312.235 h1.52
  text "Rounded" at 600.591,312.235 h1.52
  text "r125_95h55_85r100" at 619.535,312.235 h1.52
  text "33.47mil (0.850mm)" at 737.915,312.235 h1.52
  text "11.81mil (0.300mm)" at 765.847,312.235 h1.52
  text "2" at 470.326,308.425 h1.52
  text "32.01mil (0.813mm)" at 486.831,308.425 h1.52
  text "NPTH" at 516.033,308.425 h1.52
  text "Round" at 528.882,308.425 h1.52
  text "Top Layer - Bottom Layer" at 547.521,308.425 h1.52
  text "Pad" at 585.609,308.425 h1.52
  text "Rounded" at 600.591,308.425 h1.52
  text "c76hn81" at 619.535,308.425 h1.52
  text "-" at 737.915,308.425 h1.52
  text "-" at 765.847,308.425 h1.52
  text "2" at 470.326,304.615 h1.52
  text "35.04mil (0.890mm)" at 486.831,304.615 h1.52
  text "PTH" at 516.033,304.615 h1.52
  text "Round" at 528.882,304.615 h1.52
  text "Top Layer - Bottom Layer" at 547.521,304.615 h1.52
  text "Pad" at 585.609,304.615 h1.52
  text "Rounded" at 600.591,304.615 h1.52
  text "c140h89" at 619.535,304.615 h1.52
  text "-" at 737.915,304.615 h1.52
  text "-" at 765.847,304.615 h1.52
  text "2" at 470.326,300.805 h1.52
  text "47.99mil (1.219mm)" at 486.831,300.805 h1.52
  text "NPTH" at 516.033,300.805 h1.52
  text "Round" at 528.882,300.805 h1.52
  text "Top Layer - Bottom Layer" at 547.521,300.805 h1.52
  text "Pad" at 585.609,300.805 h1.52
  text "Rounded" at 600.591,300.805 h1.52
  text "c117hn122" at 619.535,300.805 h1.52
  text "-" at 737.915,300.805 h1.52
  text "-" at 765.847,300.805 h1.52
  text "4" at 470.326,296.995 h1.52
  text "125.00mil (3.175mm)" at 486.831,296.995 h1.52
  text "PTH" at 516.033,296.995 h1.52
  text "Round" at 528.882,296.995 h1.52
  text "Top Layer - Bottom Layer" at 547.521,296.995 h1.52
  text "Pad" at 585.609,296.995 h1.52
  text "Rounded" at 600.591,296.995 h1.52
  text "c432h318" at 619.535,296.995 h1.52
  text "-" at 737.915,296.995 h1.52
  text "-" at 765.847,296.995 h1.52
  text "6" at 470.326,293.185 h1.52
  text "32.28mil (0.820mm)" at 486.831,293.185 h1.52
  text "PTH" at 516.033,293.185 h1.52
  text "Round" at 528.882,293.185 h1.52
  text "Top Layer - Bottom Layer" at 547.521,293.185 h1.52
  text "Pad" at 585.609,293.185 h1.52
  text "Rounded" at 600.591,293.185 h1.52
  text "c132h82" at 619.535,293.185 h1.52
  text "-" at 737.915,293.185 h1.52
  text "-" at 765.847,293.185 h1.52
  text "A" at 456.738,292.931 h1.69
  text "6" at 470.326,289.375 h1.52
  text "42.13mil (1.070mm)" at 486.831,289.375 h1.52
  text "PTH" at 516.033,289.375 h1.52
  text "Round" at 528.882,289.375 h1.52
  text "Top Layer - Bottom Layer" at 547.521,289.375 h1.52
  text "Pad" at 585.609,289.375 h1.52
  text "(Mixed)" at 600.591,289.375 h1.52
  text "(Mixed)" at 619.535,289.375 h1.52
  text "-" at 737.915,289.375 h1.52
  text "-" at 765.847,289.375 h1.52
  text "6" at 470.326,285.565 h1.52
  text "177.17mil (4.500mm)" at 486.831,285.565 h1.52
  text "PTH" at 516.033,285.565 h1.52
  text "Round" at 528.882,285.565 h1.52
  text "Top Layer - Bottom Layer" at 547.521,285.565 h1.52
  text "Pad" at 585.609,285.565 h1.52
  text "Rounded" at 600.591,285.565 h1.52
  text "c600h450" at 619.535,285.565 h1.52
  text "-" at 737.915,285.565 h1.52
  text "-" at 765.847,285.565 h1.52
  text "20" at 470.326,281.755 h1.52
  text "27.99mil (0.711mm)" at 486.831,281.755 h1.52
  text "PTH" at 516.033,281.755 h1.52
  text "Round" at 528.882,281.755 h1.52
  text "Top Layer - Bottom Layer" at 547.521,281.755 h1.52
  text "Pad" at 585.609,281.755 h1.52
  text "(Mixed)" at 600.591,281.755 h1.52
  text "(Mixed)" at 619.535,281.755 h1.52
  text "-" at 737.915,281.755 h1.52
  text "-" at 765.847,281.755 h1.52
  text "20" at 470.326,277.945 h1.52
  text "125.98mil (3.200mm)" at 486.831,277.945 h1.52
  text "PTH" at 516.033,277.945 h1.52
  text "Round" at 528.882,277.945 h1.52
  text "Top Layer - Bottom Layer" at 547.521,277.945 h1.52
  text "Pad" at 585.609,277.945 h1.52
  text "Rounded" at 600.591,277.945 h1.52
  text "c600h320" at 619.535,277.945 h1.52
  text "-" at 737.915,277.945 h1.52
  text "-" at 765.847,277.945 h1.52
  text "38" at 470.326,274.135 h1.52
  text "39.37mil (1.000mm)" at 486.831,274.135 h1.52
  text "PTH" at 516.033,274.135 h1.52
  text "Round" at 528.882,274.135 h1.52
  text "Top Layer - Bottom Layer" at 547.521,274.135 h1.52
  text "Pad" at 585.609,274.135 h1.52
  text "(Mixed)" at 600.591,274.135 h1.52
  text "(Mixed)" at 619.535,274.135 h1.52
  text "-" at 737.915,274.135 h1.52
  text "-" at 765.847,274.135 h1.52
  text "62" at 470.326,270.325 h1.52
  text "40.16mil (1.020mm)" at 486.831,270.325 h1.52
  text "PTH" at 516.033,270.325 h1.52
  text "Round" at 528.882,270.325 h1.52
  text "Top Layer - Bottom Layer" at 547.521,270.325 h1.52
  text "Pad" at 585.609,270.325 h1.52
  text "(Mixed)" at 600.591,270.325 h1.52
  text "(Mixed)" at 619.535,270.325 h1.52
  text "-" at 737.915,270.325 h1.52
  text "-" at 765.847,270.325 h1.52
  text "66" at 470.326,266.515 h1.52
  text "17.72mil (0.450mm)" at 486.831,266.515 h1.52
  text "PTH" at 516.033,266.515 h1.52
  text "Round" at 528.882,266.515 h1.52
  text "Top Layer - Bottom Layer" at 547.521,266.515 h1.52
  text "Via" at 585.609,266.515 h1.52
  text "Rounded" at 600.591,266.515 h1.52
  text "v76h45m0mx0" at 619.535,266.515 h1.52
  text "-" at 737.915,266.515 h1.52
  text "-" at 765.847,266.515 h1.52
  text "627" at 470.326,262.705 h1.52
  text "35.43mil (0.900mm)" at 486.831,262.705 h1.52
  text "PTH" at 516.033,262.705 h1.52
  text "Round" at 528.882,262.705 h1.52
  text "Top Layer - Bottom Layer" at 547.521,262.705 h1.52
  text "Pad" at 585.609,262.705 h1.52
  text "(Mixed)" at 600.591,262.705 h1.52
  text "(Mixed)" at 619.535,262.705 h1.52
  text "-" at 737.915,262.705 h1.52
  text "-" at 765.847,262.705 h1.52
  text "1073" at 470.326,258.895 h1.52
  text "11.81mil (0.300mm)" at 486.831,258.895 h1.52
  text "PTH" at 516.033,258.895 h1.52
  text "Round" at 528.882,258.895 h1.52
  text "Top Layer - Bottom Layer" at 547.521,258.895 h1.52
  text "Via" at 585.609,258.895 h1.52
  text "Rounded" at 600.591,258.895 h1.52
  text "v51h30m0mx0" at 619.535,258.895 h1.52
  text "-" at 737.915,258.895 h1.52
  text "-" at 765.847,258.895 h1.52
  text "1938 Total" at 470.326,255.085 h1.52
  text "Slot definitions :" at 457.476,251.403 h1.52
  text "Routed Path Length" at 483.707,251.403 h1.52
  text "= Calculated from tool start centre position to tool end centre position." at 511.715,251.403 h1.52
  text "Hole Length" at 483.707,248.863 h1.52
  text "= Routed Path Length + Tool Size = Slot length as defined in the PCB layout" at 501.304,248.863 h1.52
